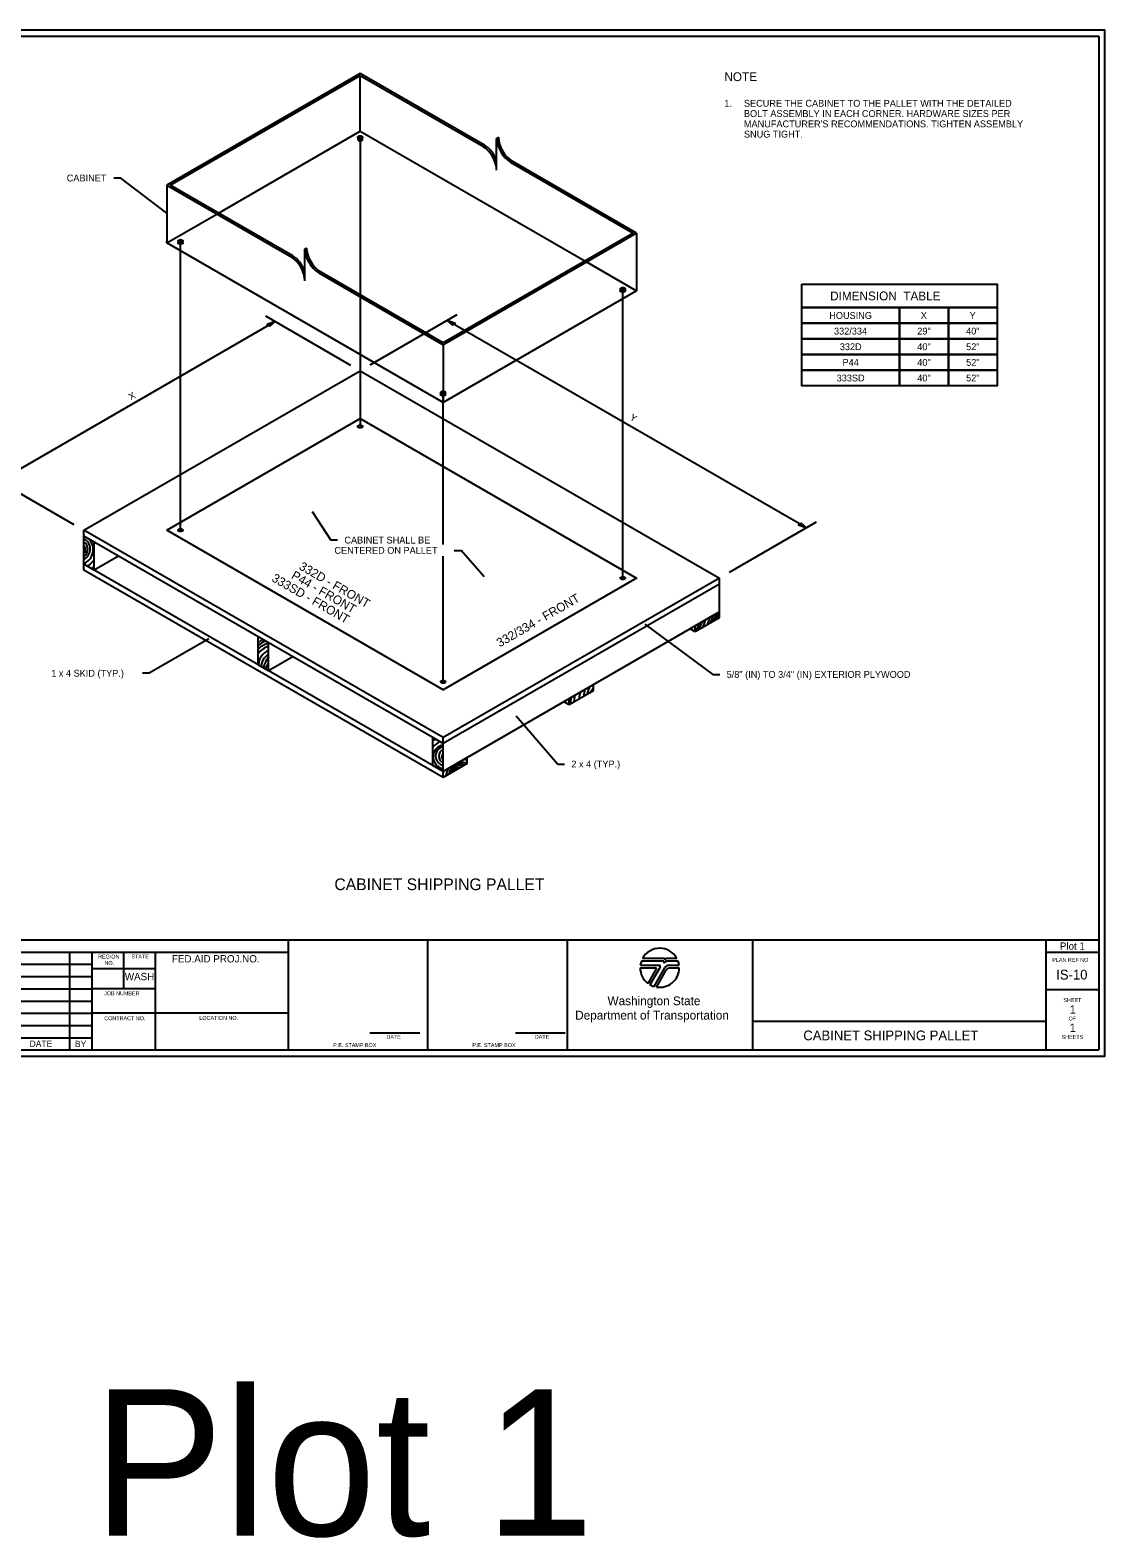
# Model space of a CAD drawing. Extents: x 99988 to 100172, y 99995 to 100047.
# Drawn here: x 100004.81 to 100015.81, y 99995.01 to 100010.44 of the extents above; entities that cross this region are included whole.
import ezdxf

# ---------------------------------------------------------------- set-up
doc = ezdxf.new("R2010")
doc.units = 0
for name, color, linetype in [('Default', 7, 'Continuous'), ('Level 1', 7, 'Continuous'), ('Level 15', 7, 'Continuous'), ('Level 2', 7, 'Continuous'), ('Level 20', 7, 'Continuous'), ('Level 3', 7, 'Continuous'), ('Level 4', 7, 'Continuous'), ('Level 40', 7, 'Continuous'), ('SH_GI_PlotLimits', 7, 'Continuous'), ('SH_GI_SheetBorder', 7, 'Continuous'), ('SH_GI_SheetLocationText', 7, 'Continuous'), ('SH_GI_SheetTextInCells', 7, 'Continuous'), ('SH_GI_TitleBlockText', 7, 'Continuous'), ('SH_GI_WSDOTLogo', 7, 'Continuous'), ('SH_RS_ConstructionNoteFlag', 7, 'Continuous'), ('SH_RS_DimensionLines', 7, 'Continuous')]:
    doc.layers.add(name, color=color, linetype=linetype)

msp = doc.modelspace()

# ---------------------------------------------------------------- linework, layer by layer
at = {"layer": 'Level 1'}
for p, q in [((100005.741, 100008.924), (100005.671, 100008.924)), ((100006.033, 100003.855), (100005.963, 100003.855)), ((100011.802, 100003.843), (100011.872, 100003.843)), ((100010.213, 100002.926), (100010.283, 100002.926))]:
    msp.add_line(p, q, dxfattribs=at)
at = {"layer": 'Level 15'}
for p, q in [((100008.192, 100009.341), (100008.192, 100006.381)), ((100006.353, 100005.319), (100006.353, 100008.279)), ((100010.879, 100004.829), (100010.879, 100007.789)), ((100009.182, 100007.524), (100008.292, 100007.01)), ((100007.322, 100007.455), (100004.493, 100005.822)), ((100007.222, 100007.512), (100008.092, 100007.01)), ((100012.759, 100005.343), (100009.082, 100007.466)), ((100009.04, 100005.173), (100009.04, 100006.728)), ((100004.393, 100005.879), (100005.263, 100005.377)), ((100012.859, 100005.401), (100011.969, 100004.887)), ((100007.96, 100005.218), (100007.89, 100005.218)), ((100009.04, 100003.768), (100009.04, 100005.053)), ((100009.154, 100005.113), (100009.224, 100005.113))]:
    msp.add_line(p, q, dxfattribs=at)
for points in [[(100007.322, 100007.455), (100007.24, 100007.423), (100007.257, 100007.417), (100007.267, 100007.408)], [(100009.082, 100007.466), (100009.137, 100007.419), (100009.147, 100007.429), (100009.163, 100007.435)], [(100006.212, 100005.319), (100008.192, 100006.462), (100011.02, 100004.829), (100009.04, 100003.686)], [(100012.759, 100005.343), (100012.704, 100005.39), (100012.694, 100005.381), (100012.677, 100005.375)]]:
    msp.add_lwpolyline(points, close=True, dxfattribs=at)
at = {"layer": 'Level 2'}
for p, q in [((100008.192, 100009.994), (100006.212, 100008.851)), ((100009.465, 100009.259), (100008.192, 100009.994)), ((100006.247, 100008.851), (100008.192, 100009.973)), ((100008.192, 100009.973), (100009.447, 100009.249)), ((100008.192, 100009.402), (100008.192, 100009.973)), ((100006.742, 100008.565), (100008.192, 100009.402)), ((100008.192, 100009.402), (100010.49, 100008.075)), ((100008.167, 100009.341), (100008.167, 100009.32)), ((100008.217, 100009.32), (100008.217, 100009.341)), ((100009.606, 100009.341), (100009.588, 100009.33)), ((100009.588, 100009.103), (100009.588, 100009.33)), ((100009.588, 100009.004), (100009.588, 100009.103)), ((100009.73, 100009.085), (100010.985, 100008.361)), ((100011.02, 100008.361), (100009.748, 100009.096)), ((100006.212, 100008.851), (100006.212, 100008.279)), ((100006.212, 100008.851), (100007.485, 100008.116)), ((100007.502, 100008.126), (100006.247, 100008.851)), ((100006.212, 100008.259), (100006.742, 100008.565)), ((100011.02, 100008.361), (100009.04, 100007.218)), ((100010.985, 100008.361), (100009.04, 100007.238)), ((100011.02, 100008.361), (100011.02, 100007.769)), ((100006.212, 100008.259), (100006.212, 100008.279)), ((100009.04, 100006.626), (100006.212, 100008.259)), ((100006.328, 100008.279), (100006.328, 100008.259)), ((100006.378, 100008.259), (100006.378, 100008.279)), ((100007.644, 100008.208), (100007.626, 100008.197)), ((100007.626, 100007.871), (100007.626, 100008.197)), ((100010.508, 100008.065), (100011.02, 100007.769)), ((100007.768, 100007.953), (100009.04, 100007.218)), ((100009.04, 100007.238), (100007.785, 100007.963)), ((100011.02, 100007.769), (100009.04, 100006.626)), ((100010.854, 100007.789), (100010.854, 100007.769)), ((100010.904, 100007.769), (100010.904, 100007.789)), ((100009.04, 100007.218), (100009.04, 100006.646)), ((100005.363, 100005.319), (100008.192, 100006.952)), ((100008.192, 100006.952), (100011.869, 100004.829)), ((100009.015, 100006.728), (100009.015, 100006.707)), ((100009.04, 100006.626), (100009.04, 100006.646)), ((100009.065, 100006.707), (100009.065, 100006.728)), ((100008.217, 100006.381), (100008.217, 100006.381)), ((100005.363, 100005.258), (100005.363, 100005.319)), ((100009.04, 100003.196), (100005.363, 100005.319)), ((100009.04, 100003.135), (100005.363, 100005.258)), ((100006.378, 100005.319), (100006.378, 100005.319)), ((100011.869, 100004.829), (100009.04, 100003.196)), ((100010.854, 100004.829), (100010.854, 100004.829)), ((100011.869, 100004.768), (100011.869, 100004.829)), ((100009.015, 100003.768), (100009.015, 100003.768)), ((100009.04, 100003.135), (100009.04, 100003.196))]:
    msp.add_line(p, q, dxfattribs=at)
for centre, major_axis, start_param, end_param in [((100008.192, 100009.32), (-0.025, 0), 5.668159, 10.114562), ((100008.192, 100009.32), (-0.025, 0), 3.926991, 5.497787), ((100009.447, 100009.085), (-0.1, 0.173), 3.926991, 5.497787), ((100009.465, 100009.096), (0.1, -0.173), 1.290759, 2.356194), ((100009.73, 100009.249), (-0.1, 0.173), 0.785398, 2.356194), ((100009.748, 100009.259), (0.1, -0.173), 3.926991, 5.497787), ((100007.768, 100008.116), (-0.1, 0.173), 0.785398, 2.356194), ((100007.785, 100008.126), (0.1, -0.173), 3.926991, 5.497787), ((100007.485, 100007.953), (-0.1, 0.173), 3.926991, 5.497787), ((100007.502, 100007.963), (0.1, -0.173), 1.290759, 2.356194)]:
    msp.add_ellipse(centre, major_axis=major_axis, ratio=0.57735, start_param=start_param, end_param=end_param, dxfattribs=at)
for centre in [(100008.192, 100009.341), (100006.353, 100008.279), (100006.353, 100008.259), (100010.879, 100007.789), (100010.879, 100007.769), (100009.04, 100006.728), (100009.04, 100006.707), (100008.192, 100006.381), (100006.353, 100005.319), (100010.879, 100004.829), (100009.04, 100003.768)]:
    msp.add_ellipse(centre, major_axis=(-0.025, 0), ratio=0.57735, dxfattribs=at)
at = {"layer": 'Level 3'}
for p, q in [((100005.363, 100004.972), (100005.363, 100005.258)), ((100005.47, 100005.197), (100005.363, 100005.258)), ((100005.47, 100004.911), (100005.47, 100005.197)), ((100005.717, 100005.054), (100005.47, 100004.911)), ((100005.47, 100004.911), (100005.363, 100004.972)), ((100005.47, 100004.911), (100005.363, 100004.972)), ((100011.869, 100004.768), (100009.04, 100003.135)), ((100011.869, 100004.482), (100011.869, 100004.768)), ((100011.869, 100004.482), (100009.04, 100002.849)), ((100007.149, 100003.942), (100007.149, 100004.227)), ((100007.255, 100004.166), (100007.149, 100004.227)), ((100007.255, 100003.88), (100007.255, 100004.166)), ((100007.502, 100004.023), (100007.255, 100003.88)), ((100007.255, 100003.88), (100007.149, 100003.942)), ((100008.934, 100002.911), (100008.934, 100003.196)), ((100009.04, 100003.135), (100008.934, 100003.196)), ((100009.04, 100002.849), (100009.04, 100003.135)), ((100009.04, 100002.849), (100008.934, 100002.911))]:
    msp.add_line(p, q, dxfattribs=at)
for centre, radius, start, end in [((100005.313, 100005.128), 0.117, 295.4546, 64.5454), ((100005.305, 100005.122), 0.155, 292.0301, 41.1435), ((100005.318, 100005.125), 0.0866, 301.5123, 58.4877), ((100005.337, 100005.121), 0.0454, 305.985, 54.015), ((100005.305, 100005.118), 0.192, 299.7904, 329.1612), ((100005.312, 100005.118), 0.231, 304.2704, 313.0352), ((100007.195, 100004.147), 0.0803, 114.76, 124.9774), ((100007.371, 100003.877), 0.37, 118.6057, 126.7543), ((100007.338, 100003.897), 0.309, 111.679, 127.7761), ((100007.292, 100003.951), 0.211, 100.0199, 132.6404), ((100007.299, 100003.957), 0.178, 104.2056, 147.3259), ((100007.315, 100003.933), 0.165, 111.3827, 177.2946), ((100007.358, 100003.903), 0.182, 124.402, 172.905), ((100007.492, 100003.841), 0.299, 142.4553, 166.443), ((100007.353, 100003.863), 0.136, 136.1963, 164.3934), ((100009.039, 100003.001), 0.192, 112.5491, 123.0896), ((100009.064, 100003), 0.162, 109.4398, 143.4597), ((100009.059, 100003), 0.122, 98.6631, 261.3369), ((100009.061, 100003.008), 0.0975, 102.2487, 257.7513), ((100009.069, 100003.006), 0.0726, 113.2796, 246.7204), ((100009.061, 100003), 0.0362, 125.5181, 234.4819)]:
    msp.add_arc(centre, radius, start, end, dxfattribs=at)
at = {"layer": 'Level 4'}
for p, q in [((100005.363, 100004.911), (100005.363, 100004.972)), ((100009.04, 100002.849), (100005.363, 100004.972)), ((100009.04, 100002.788), (100005.363, 100004.911)), ((100011.869, 100004.482), (100011.621, 100004.34)), ((100011.869, 100004.482), (100011.621, 100004.34)), ((100011.869, 100004.421), (100011.869, 100004.482)), ((100011.621, 100004.278), (100011.568, 100004.309)), ((100011.869, 100004.421), (100011.621, 100004.278)), ((100011.621, 100004.278), (100011.621, 100004.34)), ((100010.578, 100003.737), (100010.331, 100003.594)), ((100010.578, 100003.676), (100010.331, 100003.533)), ((100010.578, 100003.676), (100010.578, 100003.737)), ((100010.331, 100003.533), (100010.278, 100003.564)), ((100010.331, 100003.533), (100010.331, 100003.594)), ((100009.288, 100002.992), (100009.04, 100002.849)), ((100009.288, 100002.992), (100009.04, 100002.849)), ((100009.288, 100002.931), (100009.04, 100002.788)), ((100009.288, 100002.931), (100009.288, 100002.992)), ((100009.04, 100002.788), (100009.04, 100002.849))]:
    msp.add_line(p, q, dxfattribs=at)
for centre, radius, start, end in [((100009.998, 100004.979), 1.881, 341.066, 343.4677), ((100009.185, 100005.271), 2.766, 341.3224, 342.9595), ((100010.011, 100004.998), 1.915, 341.7926, 344.1207), ((100011.485, 100004.523), 0.386, 343.4031, 353.9056), ((100011.573, 100004.377), 0.0903, 302.1342, 351.5476), ((100011.429, 100004.478), 0.281, 316.57, 339.6925), ((100011.518, 100004.441), 0.212, 324.4064, 348.6969), ((100011.361, 100004.517), 0.418, 336.3887, 347.2928), ((100010.773, 100003.573), 0.341, 165.3815, 176.8399), ((100010.784, 100003.615), 0.303, 166.3809, 179.022), ((100010.765, 100003.597), 0.254, 152.1887, 170.3859), ((100010.7, 100003.592), 0.166, 136.9542, 156.5469), ((100010.672, 100003.541), 0.329, 168.6887, 180.0722), ((100010.742, 100003.559), 0.362, 169.2341, 179.5671), ((100009.219, 100002.802), 0.122, 69.33, 170.67), ((100009.203, 100002.831), 0.0792, 63.5713, 176.4287), ((100009.189, 100002.845), 0.0426, 66.5838, 173.4162), ((100009.225, 100002.786), 0.158, 66.4211, 98.4218), ((100009.222, 100002.79), 0.187, 69.5103, 79.3851), ((100009.222, 100002.79), 0.187, 160.6149, 166.3503), ((100009.225, 100002.786), 0.158, 141.5782, 173.5789)]:
    msp.add_arc(centre, radius, start, end, dxfattribs=at)
at = {"layer": 'Level 40'}
for points in [[(100012.711, 100007.837), (100014.711, 100007.837), (100014.711, 100007.597), (100012.711, 100007.597)], [(100012.711, 100007.597), (100013.711, 100007.597), (100013.711, 100007.437), (100012.711, 100007.437)], [(100013.711, 100007.597), (100014.211, 100007.597), (100014.211, 100007.437), (100013.711, 100007.437)], [(100014.211, 100007.597), (100014.711, 100007.597), (100014.711, 100007.437), (100014.211, 100007.437)], [(100012.711, 100007.437), (100013.711, 100007.437), (100013.711, 100007.277), (100012.711, 100007.277)], [(100013.711, 100007.437), (100014.211, 100007.437), (100014.211, 100007.277), (100013.711, 100007.277)], [(100014.211, 100007.437), (100014.711, 100007.437), (100014.711, 100007.277), (100014.211, 100007.277)], [(100012.711, 100007.277), (100013.711, 100007.277), (100013.711, 100007.117), (100012.711, 100007.117)], [(100013.711, 100007.277), (100014.211, 100007.277), (100014.211, 100007.117), (100013.711, 100007.117)], [(100014.211, 100007.277), (100014.711, 100007.277), (100014.711, 100007.117), (100014.211, 100007.117)], [(100012.711, 100007.117), (100013.711, 100007.117), (100013.711, 100006.957), (100012.711, 100006.957)], [(100013.711, 100007.117), (100014.211, 100007.117), (100014.211, 100006.957), (100013.711, 100006.957)], [(100014.211, 100007.117), (100014.711, 100007.117), (100014.711, 100006.957), (100014.211, 100006.957)], [(100012.711, 100006.957), (100013.711, 100006.957), (100013.711, 100006.797), (100012.711, 100006.797)], [(100013.711, 100006.957), (100014.211, 100006.957), (100014.211, 100006.797), (100013.711, 100006.797)], [(100014.211, 100006.957), (100014.711, 100006.957), (100014.711, 100006.797), (100014.211, 100006.797)]]:
    msp.add_lwpolyline(points, close=True, dxfattribs=at)
at = {"layer": 'SH_GI_PlotLimits'}
msp.add_lwpolyline([(99999.312, 99999.937), (100015.812, 99999.937), (100015.812, 100010.437), (99999.312, 100010.437)], close=True, dxfattribs=at)
at = {"layer": 'SH_GI_SheetBorder'}
for p, q in [((100000, 100010.375), (100015.75, 100010.375)), ((100015.75, 100010.375), (100015.75, 100000)), ((100000, 100001.126), (100015.75, 100001.126)), ((100007.457, 100000), (100007.457, 100001.126)), ((100008.883, 100000), (100008.883, 100001.126)), ((100010.309, 100001.126), (100010.309, 100000)), ((100012.205, 100001.126), (100012.205, 100000)), ((100015.208, 100001.126), (100015.208, 100000)), ((100000, 100001.001), (100007.457, 100001.001)), ((100005.216, 100001.001), (100005.216, 100000)), ((100005.445, 100001.001), (100005.445, 100000)), ((100005.772, 100000.625), (100005.772, 100001.001)), ((100006.096, 100000), (100006.096, 100001.001)), ((100015.208, 100001.001), (100015.75, 100001.001)), ((100002.182, 100000.876), (100005.447, 100000.876)), ((100002.182, 100000.751), (100005.447, 100000.751)), ((100006.096, 100000.831), (100005.447, 100000.831)), ((100000, 100000.625), (100005.447, 100000.625)), ((100006.096, 100000.625), (100005.447, 100000.625)), ((100015.208, 100000.618), (100015.75, 100000.618)), ((100000, 100000.5), (100005.447, 100000.5)), ((100000, 100000.375), (100005.447, 100000.375)), ((100007.457, 100000.375), (100005.447, 100000.375)), ((100012.205, 100000.295), (100015.208, 100000.295)), ((100000, 100000.25), (100005.447, 100000.25)), ((100000, 100000.125), (100005.447, 100000.125)), ((100008.29, 100000.173), (100008.802, 100000.173)), ((100009.78, 100000.173), (100010.291, 100000.173)), ((100000, 100000), (100015.75, 100000))]:
    msp.add_line(p, q, dxfattribs=at)
at = {"layer": 'SH_GI_WSDOTLogo'}
for p, q in [((100011.289, 100000.909), (100011.07, 100000.909)), ((100011.303, 100000.935), (100011.081, 100000.935)), ((100011.433, 100000.935), (100011.335, 100000.935)), ((100011.445, 100000.909), (100011.343, 100000.909)), ((100011.343, 100000.909), (100011.343, 100000.909)), ((100011.057, 100000.84), (100011.215, 100000.84)), ((100011.059, 100000.866), (100011.25, 100000.866)), ((100011.222, 100000.828), (100011.136, 100000.681)), ((100011.261, 100000.846), (100011.157, 100000.667)), ((100011.199, 100000.649), (100011.309, 100000.839)), ((100011.224, 100000.643), (100011.324, 100000.816)), ((100011.356, 100000.866), (100011.456, 100000.866)), ((100011.365, 100000.839), (100011.457, 100000.839))]:
    msp.add_line(p, q, dxfattribs=at)
for centre, radius, start, end in [((100011.257, 100000.84), 0.2, 28.4787, 151.532), ((100011.257, 100000.84), 0.2, 159.696, 172.5057), ((100011.289, 100000.895), 0.0148, 327.8418, 89.9985), ((100011.343, 100000.861), 0.0484, 89.9953, 147.8238), ((100011.303, 100000.926), 0.00903, 329.8742, 90.0033), ((100011.335, 100000.907), 0.0287, 90.0072, 148.1676), ((100011.257, 100000.84), 0.2, 7.4943, 20.2941), ((100011.257, 100000.84), 0.2, 179.9986, 232.8433), ((100011.215, 100000.832), 0.0082, 329.7436, 90), ((100011.257, 100000.84), 0.2, 260.5455, 359.8086), ((100011.25, 100000.853), 0.0131, 329.7683, 90), ((100011.356, 100000.812), 0.0542, 90, 149.9974), ((100011.365, 100000.792), 0.0476, 90, 150.0543), ((100011.257, 100000.84), 0.2, 239.7929, 253.0448)]:
    msp.add_arc(centre, radius, start, end, dxfattribs=at)
at = {"layer": 'SH_RS_DimensionLines'}
for p, q in [((100006.212, 100008.565), (100005.741, 100008.924)), ((100007.699, 100005.511), (100007.89, 100005.218)), ((100009.46, 100004.842), (100009.224, 100005.113)), ((100011.104, 100004.358), (100011.802, 100003.843)), ((100006.642, 100004.206), (100006.033, 100003.855)), ((100009.787, 100003.419), (100010.213, 100002.926))]:
    msp.add_line(p, q, dxfattribs=at)

# ---------------------------------------------------------------- texts
at = {"layer": 'Default'}
for s, p in [('1. ', (100011.919, 100009.654)), ('SECURE THE CABINET TO THE PALLET WITH THE DETAILED', (100012.119, 100009.654)), ('BOLT ASSEMBLY IN EACH CORNER. HARDWARE SIZES PER', (100012.119, 100009.549)), ('SNUG TIGHT.', (100012.119, 100009.338)), ("MANUFACTURER'S RECOMMENDATIONS. TIGHTEN ASSEMBLY", (100012.119, 100009.443))]:
    msp.add_text(s, height=0.07, dxfattribs=at).set_placement(p)
at = {"layer": 'Level 20'}
for s, height, p in [('NOTE', 0.09, (100011.919, 100009.916)), ('DIMENSION  TABLE', 0.09, (100013.001, 100007.672)), ('HOUSING', 0.07, (100012.992, 100007.482)), ('X', 0.07, (100013.929, 100007.482)), ('Y', 0.07, (100014.429, 100007.482)), ('332/334', 0.07, (100013.041, 100007.322)), ('29"', 0.07, (100013.893, 100007.322)), ('40"', 0.07, (100014.393, 100007.322)), ('332D', 0.07, (100013.1, 100007.162)), ('40"', 0.07, (100013.893, 100007.162)), ('52"', 0.07, (100014.393, 100007.162)), ('P44', 0.07, (100013.128, 100007.002)), ('40"', 0.07, (100013.893, 100007.002)), ('52"', 0.07, (100014.393, 100007.002)), ('333SD', 0.07, (100013.068, 100006.842)), ('40"', 0.07, (100013.893, 100006.842)), ('52"', 0.07, (100014.393, 100006.842)), ('CABINET SHALL BE', 0.07, (100008.03, 100005.183)), ('CENTERED ON PALLET', 0.07, (100007.928, 100005.078)), ('CABINET SHIPPING PALLET', 0.12, (100007.928, 100001.635))]:
    msp.add_text(s, height=height, dxfattribs=at).set_placement(p)
for s, height, rotation, p in [('X', 0.07, 29.9987, (100005.847, 100006.648)), ('Y', 0.07, 330.0271, (100010.944, 100006.454)), ('P44 - FRONT', 0.09, 330.0271, (100007.479, 100004.831)), ('332D - FRONT', 0.09, 330.0271, (100007.558, 100004.924)), ('333SD - FRONT', 0.09, 330.0271, (100007.278, 100004.803)), ('332/334 - FRONT', 0.09, 29.9987, (100009.62, 100004.119))]:
    msp.add_text(s, height=height, rotation=rotation, dxfattribs=at).set_placement(p)
at = {"layer": 'SH_GI_SheetBorder'}
msp.add_text('PLAN REF NO', height=0.04003, dxfattribs=at).set_placement((100015.275, 100000.901))
at = {"layer": 'SH_GI_SheetLocationText'}
for height, p in [(0.075, (100015.352, 100001.025)), (1.5, (100005.455, 99995.027))]:
    msp.add_text('Plot 1', height=height, dxfattribs=at).set_placement(p)
at = {"layer": 'SH_GI_SheetTextInCells'}
for s, height, p in [('REGION', 0.04, (100005.51, 100000.935)), ('NO.', 0.04, (100005.575, 100000.869)), ('STATE', 0.04, (100005.851, 100000.936)), ('FED.AID PROJ.NO.', 0.07506, (100006.265, 100000.895)), ('WASH', 0.0751, (100005.783, 100000.713)), ('JOB NUMBER', 0.04, (100005.571, 100000.559)), ('Washington State', 0.09007, (100010.723, 100000.457)), ('SHEET', 0.04, (100015.388, 100000.49)), ('CONTRACT NO.', 0.04003, (100005.573, 100000.304)), ('LOCATION NO.', 0.04003, (100006.546, 100000.307)), ('Department of Transportation', 0.09007, (100010.392, 100000.31)), ('OF', 0.04, (100015.441, 100000.301)), ('DATE', 0.04, (100008.46, 100000.114)), ('DATE', 0.04, (100009.979, 100000.114)), ('SHEETS', 0.04, (100015.37, 100000.112)), ('DATE', 0.0651, (100004.809, 100000.03)), ('BY', 0.0651, (100005.272, 100000.028)), ('P.E. STAMP BOX', 0.04003, (100007.915, 100000.029)), ('P.E. STAMP BOX', 0.04003, (100009.339, 100000.029))]:
    msp.add_text(s, height=height, dxfattribs=at).set_placement(p)
at = {"layer": 'SH_GI_TitleBlockText'}
for s, height, p in [('IS-10', 0.1, (100015.315, 100000.72)), ('1', 0.085, (100015.453, 100000.372)), ('1', 0.085, (100015.453, 100000.184)), ('CABINET SHIPPING PALLET', 0.1, (100012.727, 100000.098))]:
    msp.add_text(s, height=height, dxfattribs=at).set_placement(p)
at = {"layer": 'SH_RS_ConstructionNoteFlag'}
for s, p in [('CABINET', (100005.189, 100008.889)), ('1 x 4 SKID (TYP.)', (100005.03, 100003.82))]:
    msp.add_text(s, height=0.07, dxfattribs=at).set_placement(p)
for s, p in [('5/8" (IN) TO 3/4" (IN) EXTERIOR PLYWOOD', (100011.942, 100003.808)), ('2 x 4 (TYP.)', (100010.353, 100002.891))]:
    msp.add_text(s, height=0.07, rotation=360, dxfattribs=at).set_placement(p)

doc.saveas('drawing.dxf')
